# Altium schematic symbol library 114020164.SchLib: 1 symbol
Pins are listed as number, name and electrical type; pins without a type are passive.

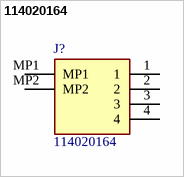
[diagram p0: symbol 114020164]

## 114020164
designator J?
Seeed Studio Accessories Grove Female Header - SMD-4P-2.0mm-90D-20Pcs; Geometry.Height: 5.45mm
footprint 114020164
pins: 1, 2, 3, 4, MP1, MP2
